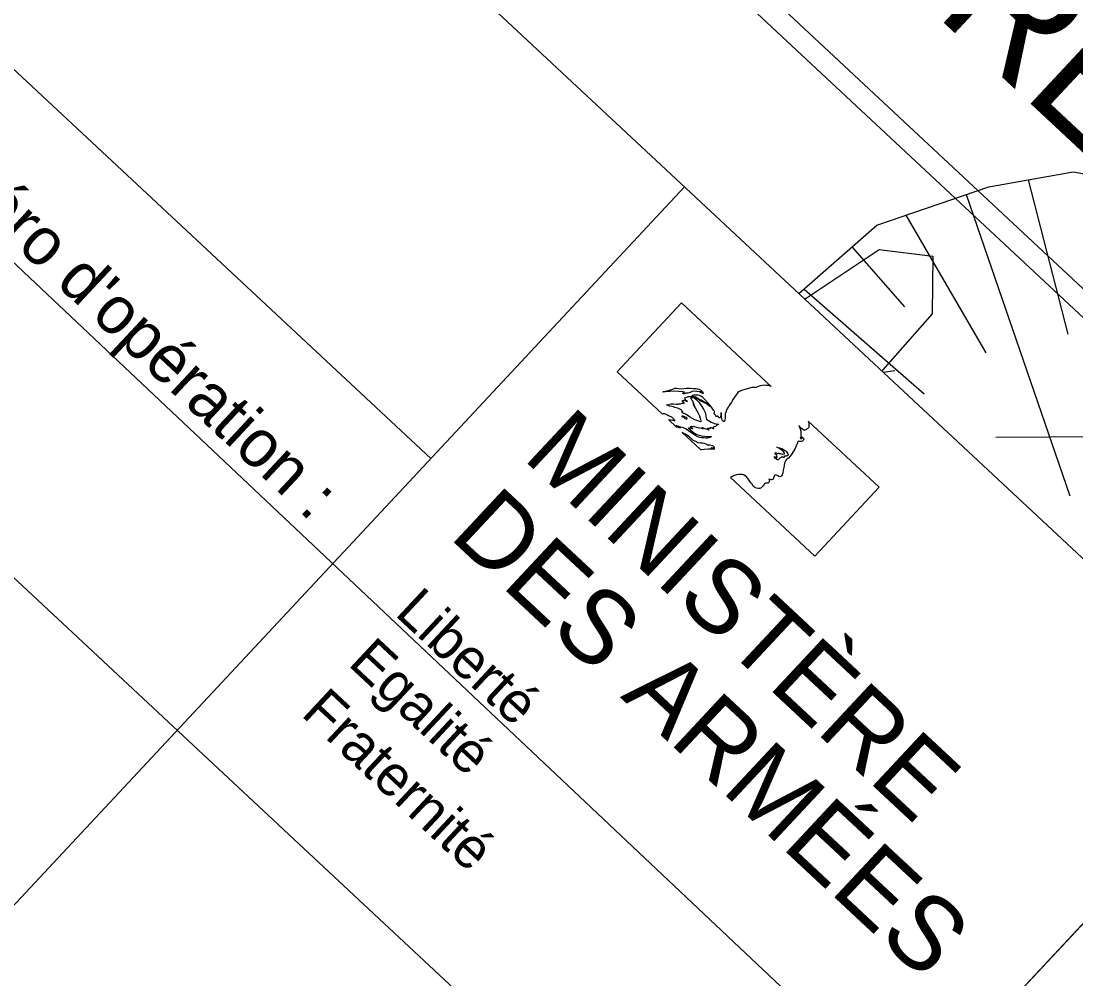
# Model space of a CAD drawing. Extents: x 343997 to 344255, y 298512 to 298767.
# Drawn here: x 344139.61 to 344156.15, y 298529.67 to 298544.71 of the extents above; entities that cross this region are included whole.
import ezdxf

# ---------------------------------------------------------------- set-up
doc = ezdxf.new("R2010")
doc.units = 0
for name, color, linetype in [('DH_CADRE -CARTOUCHE', 7, 'Continuous'), ('PC_REBAR', 7, 'Continuous'), ('PS_OBJECT', 7, 'Continuous'), ('RES_TELEPHONE SOUTERRAIN', 7, 'Continuous')]:
    doc.layers.add(name, color=color, linetype=linetype)

msp = doc.modelspace()

# ---------------------------------------------------------------- linework, layer by layer
at = {"layer": 'DH_CADRE -CARTOUCHE'}
for p, q in [((344128.033, 298554.636), (344146.034, 298537.838)), ((344124.053, 298550.372), (344151.163, 298525.072)), ((344150.014, 298542.103), (344138.074, 298529.308)), ((344148.957, 298539.199), (344149.966, 298540.281)), ((344149.966, 298540.281), (344151.374, 298538.968)), ((344149.666, 298538.537), (344148.957, 298539.199)), ((344149.887, 298538.331), (344149.76, 298538.45)), ((344153.066, 298537.388), (344151.955, 298538.426)), ((344149.976, 298538.248), (344150.264, 298537.979)), ((344150.732, 298537.543), (344152.057, 298536.306)), ((344152.057, 298536.306), (344153.066, 298537.388))]:
    msp.add_line(p, q, dxfattribs=at)
for points in [[(343997.309, 298660.673), (344147.183, 298520.807), (344245.09, 298625.72), (344095.215, 298765.586)], [(344086.014, 298601.829), (344159.123, 298533.601), (344147.183, 298520.807), (344074.074, 298589.035)], [(344136.369, 298558.619), (344159.002, 298537.497), (344162.924, 298541.7), (344140.291, 298562.822)], [(344140.308, 298562.353), (344162.455, 298541.684), (344158.986, 298537.967), (344136.838, 298558.635)], [(344150.014, 298538.881), (344149.989, 298538.886), (344149.921, 298538.893), (344149.851, 298538.895), (344149.783, 298538.892), (344149.715, 298538.885), (344149.677, 298538.881), (344149.675, 298538.884), (344149.675, 298538.887), (344149.68, 298538.89), (344149.717, 298538.898), (344149.775, 298538.911), (344149.831, 298538.93), (344149.863, 298538.943), (344149.875, 298538.945), (344149.885, 298538.943), (344149.92, 298538.937), (344149.97, 298538.935), (344150.04, 298538.941), (344150.105, 298538.942), (344150.152, 298538.94), (344150.196, 298538.936), (344150.239, 298538.927), (344150.265, 298538.915), (344150.285, 298538.899), (344150.299, 298538.883), (344150.308, 298538.866), (344150.308, 298538.862), (344150.297, 298538.862), (344150.288, 298538.865), (344150.274, 298538.874), (344150.265, 298538.873), (344150.261, 298538.877), (344150.26, 298538.883), (344150.267, 298538.887), (344150.247, 298538.888), (344150.204, 298538.891), (344150.162, 298538.894), (344150.133, 298538.89), (344150.102, 298538.878), (344150.066, 298538.866), (344150.049, 298538.866), (344150.033, 298538.866), (344150.026, 298538.869), (344150.027, 298538.864), (344150.021, 298538.86), (344150.006, 298538.857), (344149.995, 298538.855), (344149.986, 298538.858), (344149.984, 298538.861), (344149.986, 298538.866), (344149.993, 298538.87), (344150.005, 298538.872), (344150.015, 298538.872), (344150.01, 298538.877)], [(344149.975, 298538.502), (344149.978, 298538.507), (344149.987, 298538.508), (344149.997, 298538.506), (344150.011, 298538.499), (344150.025, 298538.493), (344150.035, 298538.491), (344150.042, 298538.488), (344150.044, 298538.482), (344150.042, 298538.476), (344150.048, 298538.467), (344150.051, 298538.461), (344150.047, 298538.458), (344150.038, 298538.459), (344150.025, 298538.463), (344150.011, 298538.474), (344150, 298538.485), (344149.987, 298538.49), (344149.978, 298538.496)]]:
    msp.add_lwpolyline(points, close=True, dxfattribs=at)
for points in [[(344151.271, 298538.99), (344151.238, 298538.986), (344151.201, 298538.979), (344151.169, 298538.969), (344151.149, 298538.961), (344151.139, 298538.954), (344151.132, 298538.952), (344151.12, 298538.954), (344151.1, 298538.955), (344151.067, 298538.952), (344151.031, 298538.945), (344150.994, 298538.934), (344150.945, 298538.918), (344150.906, 298538.906), (344150.873, 298538.891), (344150.85, 298538.876), (344150.838, 298538.862), (344150.821, 298538.84), (344150.796, 298538.803), (344150.776, 298538.771), (344150.749, 298538.726), (344150.724, 298538.687), (344150.715, 298538.671), (344150.707, 298538.656), (344150.696, 298538.644), (344150.685, 298538.63), (344150.68, 298538.619), (344150.674, 298538.605), (344150.67, 298538.597), (344150.667, 298538.588), (344150.67, 298538.581), (344150.663, 298538.575), (344150.659, 298538.568), (344150.66, 298538.562), (344150.662, 298538.559), (344150.654, 298538.551), (344150.652, 298538.545), (344150.652, 298538.509), (344150.649, 298538.477), (344150.644, 298538.44), (344150.639, 298538.423), (344150.634, 298538.418), (344150.627, 298538.419), (344150.617, 298538.428), (344150.606, 298538.443), (344150.597, 298538.463), (344150.593, 298538.485), (344150.592, 298538.503), (344150.591, 298538.539), (344150.59, 298538.554), (344150.588, 298538.557), (344150.585, 298538.556), (344150.581, 298538.552), (344150.582, 298538.539), (344150.582, 298538.51), (344150.58, 298538.492), (344150.574, 298538.482), (344150.567, 298538.478), (344150.558, 298538.479), (344150.551, 298538.484), (344150.546, 298538.494), (344150.538, 298538.503), (344150.53, 298538.506), (344150.522, 298538.501), (344150.513, 298538.49)], [(344151.374, 298538.968), (344151.355, 298538.974), (344151.328, 298538.983), (344151.295, 298538.988), (344151.271, 298538.99)], [(344150.019, 298538.542), (344149.995, 298538.548), (344149.976, 298538.563), (344149.973, 298538.574), (344149.975, 298538.578), (344149.989, 298538.571), (344149.966, 298538.592), (344149.97, 298538.598), (344149.951, 298538.607), (344149.928, 298538.621), (344149.91, 298538.628), (344149.884, 298538.634), (344149.862, 298538.642), (344149.839, 298538.651), (344149.813, 298538.657), (344149.779, 298538.662), (344149.755, 298538.669), (344149.737, 298538.676), (344149.737, 298538.682), (344149.743, 298538.686), (344149.761, 298538.683), (344149.774, 298538.683), (344149.777, 298538.69), (344149.778, 298538.694), (344149.797, 298538.696), (344149.841, 298538.696), (344149.886, 298538.692), (344149.906, 298538.692), (344149.913, 298538.7), (344149.945, 298538.7), (344149.96, 298538.704), (344149.974, 298538.71), (344149.992, 298538.708), (344150.005, 298538.704), (344150.001, 298538.711), (344150.005, 298538.719), (344149.993, 298538.725), (344149.982, 298538.734), (344149.979, 298538.742), (344149.979, 298538.748), (344149.984, 298538.749), (344149.994, 298538.748), (344150, 298538.744), (344149.999, 298538.751), (344150.004, 298538.755), (344150.014, 298538.756), (344150.028, 298538.749), (344150.042, 298538.739), (344150.054, 298538.735), (344150.062, 298538.737), (344150.041, 298538.75), (344150.022, 298538.769), (344150.016, 298538.782), (344150.014, 298538.789), (344150.019, 298538.793), (344150.042, 298538.801), (344150.077, 298538.811), (344150.106, 298538.813), (344150.125, 298538.811), (344150.14, 298538.807), (344150.146, 298538.802), (344150.144, 298538.796), (344150.136, 298538.791), (344150.124, 298538.785), (344150.111, 298538.786)], [(344150.111, 298538.786), (344150.105, 298538.79), (344150.116, 298538.774), (344150.13, 298538.757), (344150.141, 298538.738), (344150.146, 298538.727), (344150.145, 298538.721), (344150.136, 298538.725), (344150.146, 298538.712), (344150.16, 298538.693), (344150.162, 298538.682), (344150.157, 298538.68), (344150.148, 298538.687), (344150.181, 298538.634), (344150.221, 298538.563), (344150.246, 298538.507), (344150.262, 298538.454), (344150.267, 298538.43), (344150.269, 298538.415), (344150.266, 298538.413), (344150.236, 298538.426), (344150.177, 298538.449), (344150.093, 298538.493), (344150.053, 298538.518), (344150.041, 298538.535), (344150.032, 298538.528), (344150.019, 298538.542)], [(344150.513, 298538.49), (344150.509, 298538.502), (344150.502, 298538.515), (344150.487, 298538.529), (344150.478, 298538.542), (344150.478, 298538.553), (344150.481, 298538.564), (344150.481, 298538.576), (344150.477, 298538.586), (344150.468, 298538.599), (344150.448, 298538.629), (344150.42, 298538.667), (344150.376, 298538.72), (344150.328, 298538.771), (344150.298, 298538.797), (344150.277, 298538.812), (344150.248, 298538.826), (344150.22, 298538.833), (344150.195, 298538.835), (344150.161, 298538.833), (344150.142, 298538.831), (344150.133, 298538.829), (344150.13, 298538.823), (344150.131, 298538.819), (344150.135, 298538.816), (344150.144, 298538.813), (344150.163, 298538.811), (344150.183, 298538.806), (344150.209, 298538.791), (344150.25, 298538.772), (344150.284, 298538.753), (344150.323, 298538.73), (344150.354, 298538.711), (344150.386, 298538.683), (344150.409, 298538.659), (344150.391, 298538.674), (344150.367, 298538.691), (344150.339, 298538.708), (344150.295, 298538.731), (344150.261, 298538.747), (344150.23, 298538.765), (344150.202, 298538.782), (344150.178, 298538.793), (344150.161, 298538.798)], [(344150.161, 298538.798), (344150.19, 298538.77), (344150.236, 298538.722), (344150.276, 298538.67), (344150.31, 298538.616), (344150.335, 298538.56), (344150.347, 298538.522), (344150.35, 298538.499), (344150.351, 298538.48), (344150.36, 298538.458), (344150.377, 298538.443)], [(344149.76, 298538.45), (344149.772, 298538.449), (344149.801, 298538.445), (344149.829, 298538.44), (344149.857, 298538.433), (344149.861, 298538.433), (344149.859, 298538.439), (344149.855, 298538.446), (344149.85, 298538.452), (344149.841, 298538.459), (344149.834, 298538.465), (344149.827, 298538.476), (344149.821, 298538.484), (344149.813, 298538.491), (344149.803, 298538.493), (344149.79, 298538.498), (344149.773, 298538.505), (344149.755, 298538.516), (344149.735, 298538.526), (344149.716, 298538.534), (344149.698, 298538.54), (344149.68, 298538.54), (344149.666, 298538.537)], [(344150.134, 298538.314), (344150.137, 298538.308), (344150.138, 298538.305), (344150.134, 298538.304), (344150.125, 298538.31), (344150.12, 298538.309), (344150.115, 298538.31), (344150.108, 298538.317), (344150.099, 298538.317), (344150.091, 298538.315), (344150.087, 298538.312), (344150.083, 298538.312), (344150.08, 298538.316), (344150.074, 298538.319), (344150.069, 298538.318), (344150.071, 298538.315), (344150.079, 298538.31), (344150.087, 298538.303), (344150.105, 298538.29), (344150.151, 298538.253), (344150.179, 298538.234), (344150.208, 298538.217), (344150.242, 298538.204), (344150.279, 298538.195), (344150.324, 298538.188), (344150.363, 298538.184), (344150.401, 298538.184), (344150.424, 298538.185), (344150.431, 298538.186), (344150.432, 298538.181), (344150.428, 298538.177), (344150.416, 298538.169), (344150.396, 298538.163), (344150.37, 298538.158), (344150.342, 298538.158), (344150.314, 298538.163), (344150.283, 298538.165), (344150.251, 298538.17), (344150.234, 298538.176), (344150.213, 298538.186), (344150.175, 298538.207), (344150.128, 298538.239), (344150.075, 298538.276), (344150.038, 298538.299), (344150.005, 298538.315), (344149.979, 298538.326), (344149.951, 298538.334), (344149.926, 298538.34), (344149.913, 298538.341), (344149.905, 298538.342), (344149.903, 298538.344), (344149.902, 298538.348), (344149.897, 298538.35), (344149.884, 298538.352), (344149.876, 298538.352), (344149.874, 298538.347), (344149.877, 298538.343), (344149.884, 298538.34), (344149.894, 298538.338), (344149.911, 298538.335), (344149.935, 298538.327), (344149.948, 298538.319), (344149.931, 298538.323), (344149.905, 298538.329), (344149.887, 298538.331)], [(344150.377, 298538.443), (344150.39, 298538.436), (344150.405, 298538.424), (344150.43, 298538.411), (344150.483, 298538.388), (344150.508, 298538.382), (344150.533, 298538.38), (344150.543, 298538.382), (344150.545, 298538.373), (344150.533, 298538.366), (344150.517, 298538.355), (344150.5, 298538.344), (344150.484, 298538.337), (344150.471, 298538.335), (344150.463, 298538.328), (344150.46, 298538.323), (344150.46, 298538.316), (344150.466, 298538.31), (344150.467, 298538.306), (344150.461, 298538.307), (344150.452, 298538.314), (344150.438, 298538.32), (344150.424, 298538.321), (344150.421, 298538.32), (344150.422, 298538.316), (344150.428, 298538.312), (344150.423, 298538.31), (344150.417, 298538.314), (344150.409, 298538.317), (344150.402, 298538.313), (344150.394, 298538.304), (344150.387, 298538.308), (344150.376, 298538.309), (344150.374, 298538.307), (344150.375, 298538.303), (344150.379, 298538.299), (344150.389, 298538.292), (344150.4, 298538.288), (344150.393, 298538.287), (344150.366, 298538.297), (344150.336, 298538.306), (344150.31, 298538.314), (344150.301, 298538.319), (344150.293, 298538.323), (344150.287, 298538.321), (344150.284, 298538.317), (344150.289, 298538.312), (344150.297, 298538.309), (344150.306, 298538.305), (344150.303, 298538.304), (344150.281, 298538.308), (344150.229, 298538.321), (344150.15, 298538.34), (344150.141, 298538.339), (344150.136, 298538.336), (344150.132, 298538.335), (344150.129, 298538.34), (344150.123, 298538.344), (344150.117, 298538.342), (344150.108, 298538.338), (344150.104, 298538.334), (344150.105, 298538.329), (344150.113, 298538.323), (344150.124, 298538.321), (344150.134, 298538.314)], [(344151.955, 298538.426), (344151.962, 298538.397), (344151.964, 298538.361), (344151.961, 298538.335), (344151.956, 298538.322), (344151.948, 298538.312), (344151.937, 298538.305), (344151.926, 298538.299), (344151.914, 298538.291), (344151.898, 298538.286), (344151.887, 298538.286), (344151.871, 298538.294), (344151.849, 298538.31), (344151.824, 298538.336), (344151.807, 298538.36), (344151.819, 298538.332), (344151.829, 298538.307), (344151.838, 298538.269), (344151.84, 298538.235), (344151.838, 298538.207), (344151.839, 298538.198), (344151.845, 298538.188), (344151.852, 298538.18), (344151.853, 298538.176), (344151.849, 298538.171), (344151.842, 298538.171), (344151.836, 298538.171), (344151.83, 298538.168), (344151.828, 298538.163), (344151.83, 298538.159), (344151.835, 298538.155), (344151.842, 298538.154), (344151.851, 298538.156), (344151.861, 298538.162), (344151.872, 298538.163), (344151.877, 298538.161), (344151.883, 298538.15), (344151.882, 298538.135), (344151.875, 298538.121), (344151.865, 298538.111), (344151.848, 298538.107), (344151.824, 298538.109), (344151.805, 298538.11), (344151.797, 298538.107), (344151.792, 298538.101), (344151.788, 298538.093), (344151.786, 298538.08), (344151.766, 298538.037), (344151.741, 298537.985), (344151.713, 298537.938), (344151.699, 298537.914), (344151.672, 298537.876), (344151.642, 298537.846), (344151.62, 298537.83), (344151.608, 298537.819), (344151.599, 298537.804), (344151.59, 298537.789), (344151.584, 298537.766)], [(344150.264, 298537.979), (344150.28, 298537.982), (344150.319, 298537.986), (344150.385, 298537.991), (344150.431, 298537.991), (344150.468, 298537.988), (344150.481, 298537.991), (344150.486, 298537.994), (344150.482, 298537.996), (344150.474, 298537.997), (344150.459, 298537.999), (344150.446, 298538), (344150.436, 298538.002), (344150.432, 298538.005), (344150.433, 298538.008), (344150.436, 298538.01), (344150.444, 298538.009), (344150.473, 298538.007), (344150.487, 298538.005), (344150.478, 298538.009), (344150.481, 298538.012), (344150.482, 298538.015), (344150.478, 298538.019), (344150.467, 298538.029), (344150.456, 298538.036), (344150.428, 298538.046), (344150.404, 298538.049), (344150.381, 298538.048), (344150.372, 298538.049), (344150.366, 298538.054), (344150.363, 298538.061), (344150.355, 298538.065), (344150.328, 298538.073), (344150.295, 298538.078), (344150.262, 298538.081), (344150.227, 298538.088), (344150.209, 298538.092), (344150.214, 298538.098), (344150.204, 298538.102), (344150.19, 298538.106), (344150.164, 298538.116), (344150.144, 298538.127), (344150.127, 298538.142), (344150.092, 298538.177), (344150.073, 298538.191), (344150.048, 298538.206), (344150.023, 298538.221), (344149.976, 298538.248)], [(344151.462, 298538.016), (344151.503, 298538.009), (344151.54, 298537.994), (344151.566, 298537.981), (344151.588, 298537.965), (344151.606, 298537.954), (344151.615, 298537.943), (344151.624, 298537.931), (344151.636, 298537.911), (344151.64, 298537.902), (344151.637, 298537.893), (344151.625, 298537.881), (344151.607, 298537.877), (344151.587, 298537.876), (344151.579, 298537.879), (344151.576, 298537.875), (344151.578, 298537.868), (344151.577, 298537.861), (344151.57, 298537.856), (344151.561, 298537.857), (344151.554, 298537.863), (344151.543, 298537.864), (344151.528, 298537.863), (344151.527, 298537.857), (344151.516, 298537.848), (344151.505, 298537.84), (344151.495, 298537.827), (344151.486, 298537.818), (344151.474, 298537.817), (344151.459, 298537.826), (344151.442, 298537.841), (344151.428, 298537.857), (344151.421, 298537.87), (344151.435, 298537.859), (344151.447, 298537.851), (344151.456, 298537.85), (344151.463, 298537.856), (344151.466, 298537.859), (344151.465, 298537.868), (344151.457, 298537.868), (344151.458, 298537.875), (344151.459, 298537.882), (344151.454, 298537.89), (344151.444, 298537.9), (344151.436, 298537.917), (344151.436, 298537.93), (344151.439, 298537.933), (344151.45, 298537.928), (344151.456, 298537.921), (344151.46, 298537.914), (344151.467, 298537.915), (344151.475, 298537.92), (344151.485, 298537.923), (344151.49, 298537.922), (344151.496, 298537.916), (344151.502, 298537.916), (344151.511, 298537.916), (344151.531, 298537.914), (344151.55, 298537.91), (344151.571, 298537.911), (344151.583, 298537.915), (344151.584, 298537.92), (344151.578, 298537.933), (344151.56, 298537.954), (344151.54, 298537.972)], [(344151.54, 298537.972), (344151.518, 298537.986), (344151.49, 298538.002), (344151.462, 298538.016)], [(344151.584, 298537.766), (344151.575, 298537.728), (344151.571, 298537.698), (344151.563, 298537.656), (344151.557, 298537.615), (344151.547, 298537.582), (344151.537, 298537.569), (344151.522, 298537.558), (344151.509, 298537.553), (344151.495, 298537.557), (344151.476, 298537.567), (344151.457, 298537.576), (344151.445, 298537.58), (344151.436, 298537.578), (344151.427, 298537.571), (344151.42, 298537.562), (344151.414, 298537.548), (344151.411, 298537.531), (344151.403, 298537.517), (344151.392, 298537.509), (344151.377, 298537.507), (344151.355, 298537.51), (344151.342, 298537.514), (344151.337, 298537.515), (344151.335, 298537.513), (344151.34, 298537.505), (344151.345, 298537.495), (344151.346, 298537.489), (344151.342, 298537.483), (344151.34, 298537.475), (344151.336, 298537.461), (344151.327, 298537.453), (344151.317, 298537.45), (344151.3, 298537.45), (344151.284, 298537.452), (344151.271, 298537.449), (344151.265, 298537.444), (344151.26, 298537.437), (344151.256, 298537.426), (344151.249, 298537.41), (344151.236, 298537.398), (344151.214, 298537.381), (344151.193, 298537.371), (344151.174, 298537.368), (344151.142, 298537.373), (344151.117, 298537.385), (344151.098, 298537.401), (344151.086, 298537.413), (344151.08, 298537.423), (344151.078, 298537.43), (344151.07, 298537.44), (344151.054, 298537.458), (344151.032, 298537.489), (344151.009, 298537.521), (344150.985, 298537.55), (344150.963, 298537.57), (344150.94, 298537.583), (344150.921, 298537.589), (344150.898, 298537.59), (344150.867, 298537.589), (344150.827, 298537.582), (344150.801, 298537.575), (344150.779, 298537.566), (344150.748, 298537.553), (344150.732, 298537.543)]]:
    msp.add_lwpolyline(points, dxfattribs=at)
at = {"layer": 'PC_REBAR'}
msp.add_lwpolyline([(344151.906, 298540.336), (344151.921, 298540.357), (344153.064, 298541.118), (344153.906, 298541.015), (344153.897, 298540.11), (344153.124, 298539.23), (344153.113, 298539.211)], dxfattribs=at)
at = {"layer": 'PS_OBJECT'}
for p, q in [((344155.402, 298542.214), (344156.027, 298539.793)), ((344154.431, 298541.984), (344156.057, 298537.254)), ((344153.485, 298541.659), (344154.742, 298539.496)), ((344152.641, 298541.159), (344153.466, 298540.221)), ((344151.89, 298540.499), (344153.772, 298538.853)), ((344153.128, 298539.196), (344153.314, 298539.222))]:
    msp.add_line(p, q, dxfattribs=at)
for points in [[(344151.808, 298540.428), (344153.03, 298541.502), (344154.786, 298542.106), (344156.109, 298542.339), (344158.437, 298541.926), (344160.993, 298541.536), (344163.377, 298540.879), (344164.858, 298540.404), (344166.51, 298540.165), (344168.092, 298540.549), (344170.181, 298541.073), (344172.111, 298541.203), (344174.024, 298541.13), (344175.756, 298541.301)], [(344154.898, 298538.173), (344172.574, 298538.285), (344178.724, 298539.008), (344183.717, 298539.783)]]:
    msp.add_lwpolyline(points, dxfattribs=at)
at = {"layer": 'RES_TELEPHONE SOUTERRAIN'}
msp.add_lwpolyline([(344006.37, 298666.609), (344159.504, 298522.019), (344160.824, 298520.82), (344163.6, 298518.226)], dxfattribs=at)

# ---------------------------------------------------------------- texts
at = {"layer": 'DH_CADRE -CARTOUCHE'}
for s, height, p in [('DIFFUSION RESTREINTE', 1.92832, (344138.214, 298559.485)), ("Numéro d'opération :", 0.75, (344137.325, 298543.204)), ('MINISTÈRE', 1.1603, (344147.456, 298537.846)), ('DES', 1.1603, (344146.302, 298536.609)), ('Liberté', 0.6381, (344145.451, 298535.391)), ('Egalité', 0.6381, (344144.717, 298534.605)), ('ARMÉES', 1.1603, (344148.994, 298534.097)), ('Fraternité', 0.6381, (344143.98, 298533.815))]:
    msp.add_text(s, height=height, rotation=316.9784, dxfattribs=at).set_placement(p)

doc.saveas('drawing.dxf')
